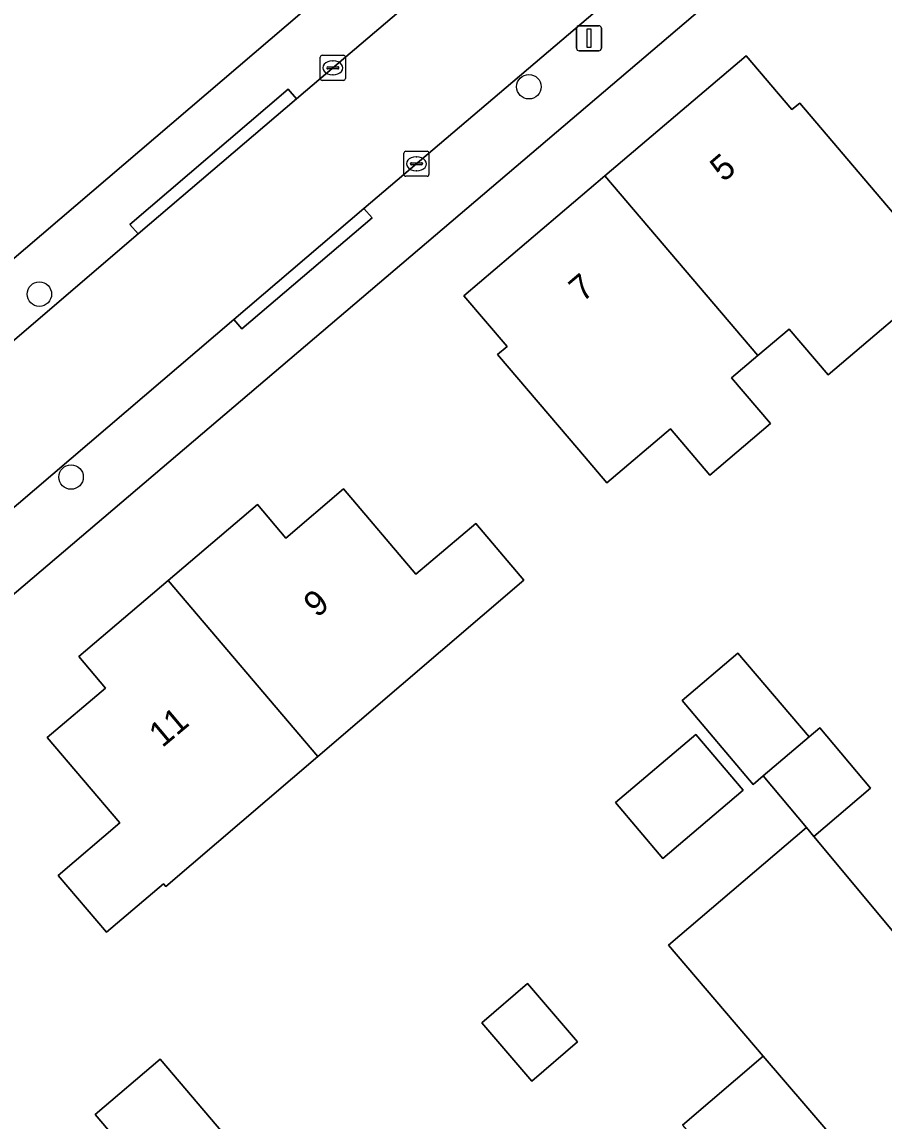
# Model space of a CAD drawing. Extents: x 161772 to 163126, y 383092 to 383917.
# Drawn here: x 162384.01 to 162418.44, y 383339.05 to 383382.94 of the extents above; entities that cross this region are included whole.
import ezdxf

# ---------------------------------------------------------------- set-up
doc = ezdxf.new("R2010")
doc.units = 0
for name, color, linetype in [('IMGEO_Boom', 7, 'Continuous'), ('IMGEO_Erf', 7, 'Continuous'), ('IMGEO_Kolk', 7, 'Continuous'), ('IMGEO_Lichtmast', 7, 'Continuous'), ('IMGEO_Pand', 7, 'Continuous'), ('IMGEO_Pand_nummerreeks', 7, 'Continuous'), ('IMGEO_Rijbaan_lokaal_open', 7, 'Continuous'), ('IMGEO_Voetpad_open', 7, 'Continuous')]:
    doc.layers.add(name, color=color, linetype=linetype)

msp = doc.modelspace()

# ---------------------------------------------------------------- linework, layer by layer
at = {"layer": 'IMGEO_Boom'}
for centre in [(162404.256, 383380.353), (162384.703, 383372.07), (162385.97, 383364.766)]:
    msp.add_circle(centre, 0.489, dxfattribs=at)
at = {"layer": 'IMGEO_Erf'}
for points in [[(162439.546, 383475.883), (162426.801, 383475.456), (162425.429, 383475.046), (162424.669, 383474.563), (162400.868, 383453.897), (162399.336, 383452.584), (162328.478, 383391.862), (162318.405, 383382.124), (162326.388, 383374.044), (162352.897, 383347.213), (162466.894, 383444.571), (162467.039, 383444.858), (162466.94, 383445.164), (162440.986, 383475.293)], [(162461.918, 383426.682), (162359.973, 383339.918)], [(162410.394, 383338.881), (162413.609, 383341.644), (162409.834, 383346.065), (162415.339, 383350.767), (162413.619, 383352.834), (162413.216, 383352.492), (162410.374, 383355.841), (162412.606, 383357.735), (162415.448, 383354.385), (162415.871, 383354.744), (162417.905, 383352.345), (162415.631, 383350.416), (162421.436, 383343.443)]]:
    msp.add_lwpolyline(points, dxfattribs=at)
for points in [[(162416.204, 383368.844), (162414.645, 383370.676), (162413.402, 383369.618), (162412.353, 383368.725), (162413.903, 383366.904), (162411.481, 383364.843), (162409.912, 383366.688), (162407.374, 383364.528), (162406.247, 383365.853), (162403.006, 383369.66), (162403.382, 383369.98), (162401.662, 383372.001), (162407.295, 383376.795), (162412.932, 383381.592), (162414.764, 383379.439), (162415.071, 383379.701), (162418.311, 383375.894), (162420.906, 383372.845)], [(162389.751, 383348.414), (162389.664, 383348.515), (162387.381, 383346.589), (162385.45, 383348.858), (162387.917, 383350.958), (162385.021, 383354.361), (162387.348, 383356.34), (162386.28, 383357.595), (162389.845, 383360.629), (162393.41, 383363.663), (162394.546, 383362.329), (162396.85, 383364.289), (162399.746, 383360.886), (162402.131, 383362.915), (162404.058, 383360.65), (162395.824, 383353.608)], [(162412.815, 383352.255), (162409.611, 383349.536), (162407.718, 383351.767), (162410.922, 383354.486)], [(162404.367, 383340.647), (162402.372, 383342.968), (162404.198, 383344.537), (162406.192, 383342.216)], [(162391.177, 383334.315), (162386.93, 383339.305), (162389.532, 383341.519), (162393.779, 383336.53)]]:
    msp.add_lwpolyline(points, close=True, dxfattribs=at)
at = {"layer": 'IMGEO_Kolk'}
for p, q in [((162395.924, 383380.681), (162395.924, 383381.533)), ((162395.999, 383381.607), (162396.851, 383381.607)), ((162396.412, 383381.387), (162396.437, 383381.387)), ((162396.925, 383381.533), (162396.925, 383380.681)), ((162396.183, 383381.101), (162396.183, 383381.113)), ((162396.621, 383381.064), (162396.223, 383381.064)), ((162396.226, 383381.15), (162396.624, 383381.15)), ((162396.435, 383380.827), (162396.41, 383380.827)), ((162396.667, 383381.113), (162396.667, 383381.101)), ((162396.851, 383380.607), (162395.999, 383380.607)), ((162399.338, 383377.775), (162400.19, 383377.775)), ((162399.263, 383376.849), (162399.263, 383377.701)), ((162399.565, 383377.318), (162399.963, 383377.318)), ((162399.751, 383377.555), (162399.776, 383377.555)), ((162400.264, 383377.701), (162400.264, 383376.849)), ((162399.522, 383377.269), (162399.522, 383377.281)), ((162399.96, 383377.232), (162399.562, 383377.232)), ((162399.774, 383376.995), (162399.749, 383376.995)), ((162400.006, 383377.281), (162400.006, 383377.269)), ((162400.19, 383376.775), (162399.338, 383376.775))]:
    msp.add_line(p, q, dxfattribs=at)
for points in [[(162395.924, 383380.681), (162395.924, 383381.533)], [(162395.999, 383381.607), (162396.851, 383381.607)], [(162396.925, 383381.533), (162396.925, 383380.681)], [(162396.851, 383380.607), (162395.999, 383380.607)], [(162399.338, 383377.775), (162400.19, 383377.775)], [(162399.263, 383376.849), (162399.263, 383377.701)], [(162400.264, 383377.701), (162400.264, 383376.849)], [(162400.19, 383376.775), (162399.338, 383376.775)]]:
    msp.add_lwpolyline(points, dxfattribs=at)
for centre, radius, start, end in [((162396.001, 383381.531), 0.0765, 91.552, 178.448), ((162396.001, 383381.531), 0.0765, 91.552, 178.448), ((162396.849, 383381.531), 0.0765, 1.552, 88.448), ((162396.849, 383381.531), 0.0765, 1.552, 88.448), ((162396.223, 383381.11), 0.0403, 85.8775, 175.7526), ((162396.22, 383381.1), 0.0366, 178.938, 274.7102), ((162396.624, 383381.107), 0.043, 264.8664, 352.4533), ((162396.628, 383381.112), 0.0386, 1.7309, 96.639), ((162396.001, 383380.683), 0.0765, 181.552, 268.448), ((162396.001, 383380.683), 0.0765, 181.552, 268.448), ((162396.849, 383380.683), 0.0765, 271.552, 358.448), ((162396.849, 383380.683), 0.0765, 271.552, 358.448), ((162399.34, 383377.699), 0.0765, 91.552, 178.448), ((162399.34, 383377.699), 0.0765, 91.552, 178.448), ((162400.188, 383377.699), 0.0765, 1.552, 88.448), ((162400.188, 383377.699), 0.0765, 1.552, 88.448), ((162399.562, 383377.278), 0.0403, 85.8775, 175.7526), ((162399.967, 383377.28), 0.0386, 1.7309, 96.639), ((162399.34, 383376.851), 0.0765, 181.552, 268.448), ((162399.34, 383376.851), 0.0765, 181.552, 268.448), ((162399.559, 383377.268), 0.0366, 178.938, 274.7102), ((162399.963, 383377.275), 0.043, 264.8664, 352.4533), ((162400.188, 383376.851), 0.0765, 271.552, 358.448), ((162400.188, 383376.851), 0.0765, 271.552, 358.448)]:
    msp.add_arc(centre, radius, start, end, dxfattribs=at)
for centre, major_axis, ratio, start_param, end_param in [((162396.411, 383381.107), (-0.387, 0.002), 0.722429, 4.712389, 7.853982), ((162396.436, 383381.107), (-0.39, 0.002), 0.717154, 1.570796, 4.712389), ((162399.75, 383377.275), (-0.387, 0.002), 0.722429, 4.712389, 7.853982), ((162399.775, 383377.275), (-0.39, 0.002), 0.717154, 1.570796, 4.712389)]:
    msp.add_ellipse(centre, major_axis=major_axis, ratio=ratio, start_param=start_param, end_param=end_param, dxfattribs=at)
at = {"layer": 'IMGEO_Lichtmast'}
for p, q in [((162406.161, 383381.889), (162406.161, 383382.689)), ((162406.161, 383382.689), (162406.161, 383381.889)), ((162406.261, 383382.789), (162407.051, 383382.789)), ((162407.051, 383382.789), (162406.261, 383382.789)), ((162407.151, 383382.689), (162407.151, 383381.889)), ((162407.151, 383381.889), (162407.151, 383382.689)), ((162407.051, 383381.789), (162406.261, 383381.789)), ((162406.261, 383381.789), (162407.051, 383381.789))]:
    msp.add_line(p, q, dxfattribs=at)
msp.add_lwpolyline([(162406.581, 383382.664), (162406.731, 383382.664), (162406.731, 383381.914), (162406.581, 383381.914), (162406.581, 383382.664)], dxfattribs=at)
for centre, start, end in [((162406.261, 383382.689), 90, 180), ((162406.261, 383382.689), 90, 180), ((162407.051, 383382.689), 0, 90), ((162407.051, 383382.689), 360, 90), ((162406.261, 383381.889), 180, 270), ((162406.261, 383381.889), 180, 270), ((162407.051, 383381.889), 270, 0), ((162407.051, 383381.889), 270, 0)]:
    msp.add_arc(centre, 0.1, start, end, dxfattribs=at)
at = {"layer": 'IMGEO_Pand'}
for points in [[(162413.402, 383369.618), (162414.645, 383370.676), (162416.204, 383368.844), (162420.906, 383372.845), (162418.311, 383375.894), (162415.071, 383379.701), (162414.764, 383379.439), (162412.932, 383381.592), (162407.295, 383376.795)], [(162413.402, 383369.618), (162407.295, 383376.795), (162401.662, 383372.001), (162403.382, 383369.98), (162403.006, 383369.66), (162406.247, 383365.853), (162407.374, 383364.528), (162409.912, 383366.688), (162411.481, 383364.843), (162413.903, 383366.904), (162412.353, 383368.725)], [(162395.824, 383353.608), (162404.058, 383360.65), (162402.131, 383362.915), (162399.746, 383360.886), (162396.85, 383364.289), (162394.546, 383362.329), (162393.41, 383363.663), (162389.845, 383360.629)], [(162395.824, 383353.608), (162389.845, 383360.629), (162386.28, 383357.595), (162387.348, 383356.34), (162385.021, 383354.361), (162387.917, 383350.958), (162385.45, 383348.858), (162387.381, 383346.589), (162389.664, 383348.515), (162389.751, 383348.414)], [(162412.606, 383357.735), (162410.374, 383355.841), (162413.216, 383352.492), (162413.619, 383352.834), (162415.448, 383354.385)], [(162412.815, 383352.255), (162410.922, 383354.486), (162407.718, 383351.767), (162409.611, 383349.536)], [(162415.448, 383354.385), (162413.619, 383352.834), (162415.339, 383350.767), (162415.631, 383350.416), (162417.905, 383352.345), (162415.871, 383354.744)], [(162421.436, 383343.443), (162415.631, 383350.416), (162415.339, 383350.767), (162409.834, 383346.065), (162413.609, 383341.644), (162415.32, 383339.649), (162418.447, 383336.002), (162424.095, 383329.453), (162425.001, 383330.227), (162429.457, 383334.039), (162422.838, 383341.759)], [(162404.367, 383340.647), (162406.192, 383342.216), (162404.198, 383344.537), (162402.372, 383342.968)], [(162391.177, 383334.315), (162393.779, 383336.53), (162389.532, 383341.519), (162386.93, 383339.305)], [(162413.609, 383341.644), (162410.394, 383338.881), (162414.152, 383334.508), (162412.553, 383333.134), (162413.288, 383332.278), (162412.353, 383331.474), (162412.82, 383330.892), (162418.31, 383324.504), (162424.095, 383329.453), (162418.447, 383336.002), (162415.32, 383339.649)]]:
    msp.add_lwpolyline(points, close=True, dxfattribs=at)
at = {"layer": 'IMGEO_Rijbaan_lokaal_open'}
msp.add_lwpolyline([(162406.665, 383389.811), (162396.585, 383381.239), (162394.968, 383379.876), (162388.646, 383374.474), (162377.951, 383365.322), (162376.079, 383363.71), (162370.876, 383359.251), (162358.215, 383348.491), (162354.626, 383345.431), (162353.931, 383344.839), (162353.291, 383344.405), (162357.022, 383340.671), (162357.578, 383341.298), (162358.156, 383341.791), (162374.059, 383355.357), (162379.237, 383359.806), (162381.654, 383361.832), (162392.472, 383371.061), (162397.667, 383375.493), (162410.454, 383386.374)], dxfattribs=at)
at = {"layer": 'IMGEO_Voetpad_open'}
for points in [[(162464.712, 383439.31), (162467.401, 383441.644), (162468.583, 383442.649), (162469.273, 383443.237), (162466.94, 383445.164), (162467.039, 383444.858), (162466.894, 383444.571), (162352.897, 383347.213), (162350.426, 383345.321), (162350.947, 383344.803)], [(162357.311, 383338.364), (162357.692, 383337.967), (162359.973, 383339.918), (162461.918, 383426.682)], [(162353.291, 383344.405), (162353.931, 383344.839), (162354.626, 383345.431), (162358.215, 383348.491), (162370.876, 383359.251), (162370.551, 383359.63), (162375.754, 383364.089), (162376.079, 383363.71), (162377.951, 383365.322), (162388.646, 383374.474), (162388.322, 383374.854), (162394.644, 383380.256), (162394.968, 383379.876), (162396.585, 383381.239), (162406.665, 383389.811)], [(162410.454, 383386.374), (162397.667, 383375.493), (162397.991, 383375.113), (162392.796, 383370.681), (162392.472, 383371.061), (162381.654, 383361.832), (162379.237, 383359.806), (162379.562, 383359.427), (162374.384, 383354.978), (162374.059, 383355.357), (162358.156, 383341.791), (162357.578, 383341.298), (162357.022, 383340.671)]]:
    msp.add_lwpolyline(points, dxfattribs=at)
for points in [[(162394.968, 383379.876), (162394.644, 383380.256), (162388.322, 383374.854), (162388.646, 383374.474)], [(162392.472, 383371.061), (162392.796, 383370.681), (162397.991, 383375.113), (162397.667, 383375.493)]]:
    msp.add_lwpolyline(points, close=True, dxfattribs=at)

# ---------------------------------------------------------------- texts
at = {"layer": 'IMGEO_Pand_nummerreeks'}
for s, rotation, p in [('5', 40.3985, (162412.03, 383376.518)), ('7', 40.3985, (162406.395, 383371.722)), ('9', 40.0065, (162395.79, 383359.118)), ('11', 40.0065, (162389.611, 383353.932))]:
    msp.add_text(s, height=1, rotation=rotation, dxfattribs=at).set_placement(p)

doc.saveas('drawing.dxf')
